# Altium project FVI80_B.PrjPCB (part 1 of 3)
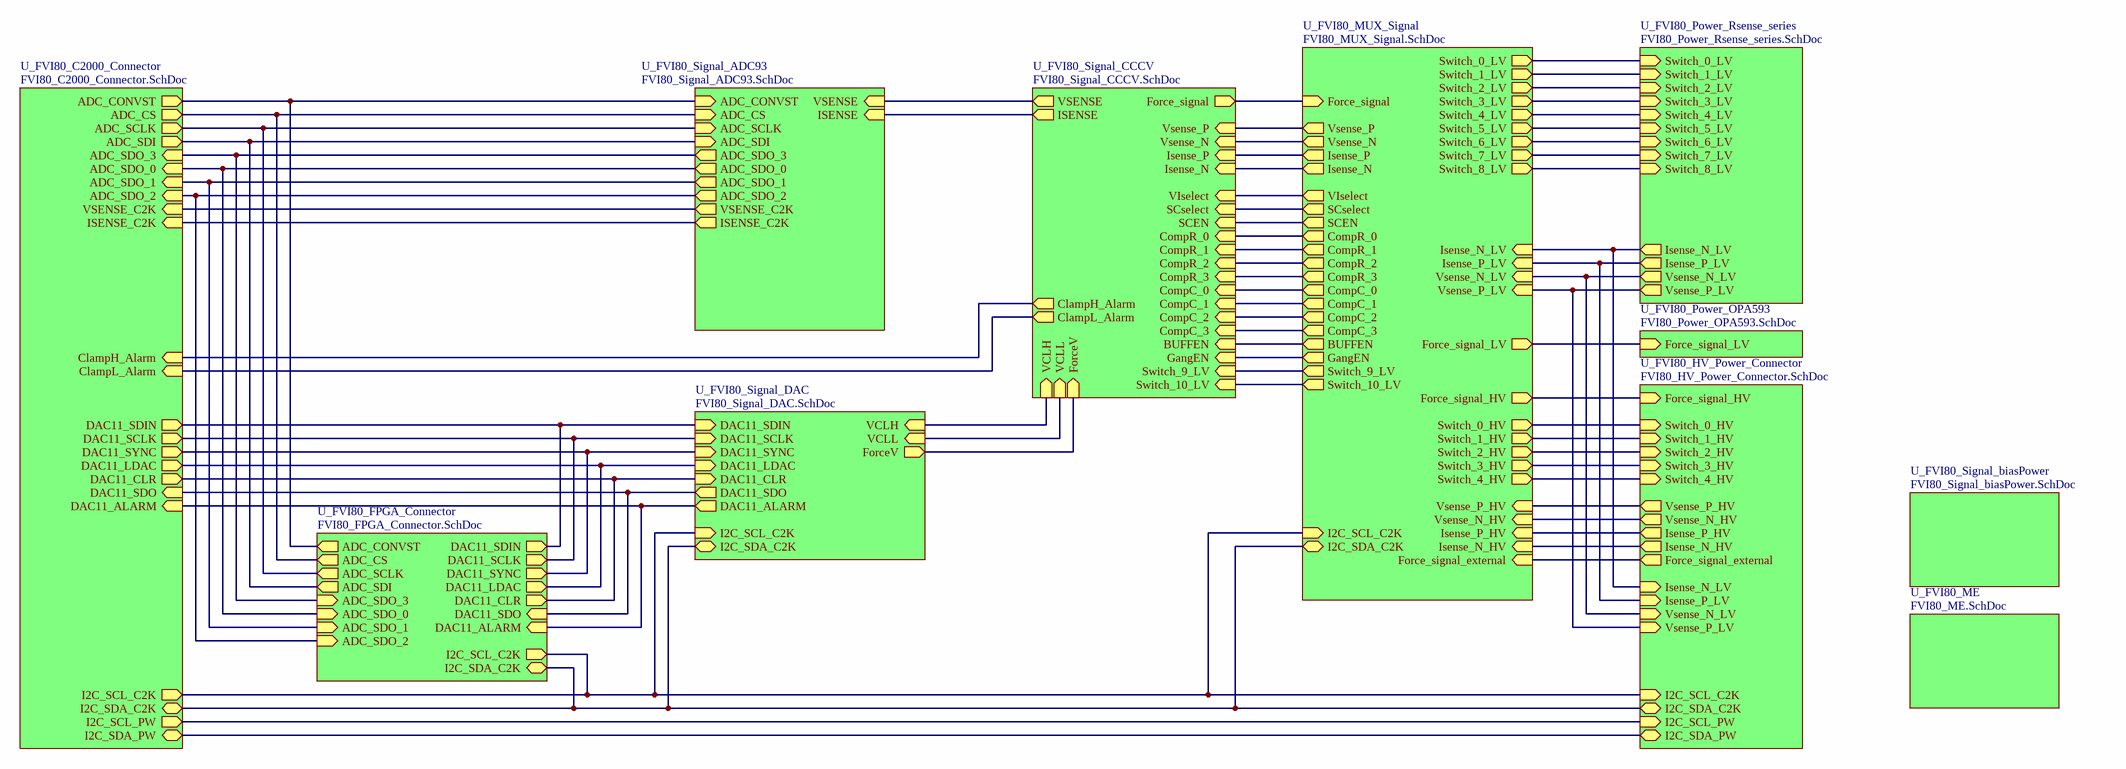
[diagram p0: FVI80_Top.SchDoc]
CopyrightYear: 2025; EVM_orderable: Developing; PCB_Rev: B; PRJ_Customer: Public Release; PRJ_Number: INDSYS-3257; PRJ_Title: FVI80 for ATE; SCH_Rev: B; TechSupport: http://www.ti.com/support; TID: TIDA-010962
12 sheets, 489 parts. Net scope: hierarchical (ports join the sheet entries above them; power ports are global).
Board file: FVI80PCB_B.PcbDoc
Sheets:
  FVI80_Top.SchDoc
    U_FVI80_ME = FVI80_ME.SchDoc
    U_FVI80_Power_OPA593 = FVI80_Power_OPA593.SchDoc
    U_FVI80_Signal_biasPower = FVI80_Signal_biasPower.SchDoc
    U_FVI80_Signal_DAC = FVI80_Signal_DAC.SchDoc
    U_FVI80_Signal_CCCV = FVI80_Signal_CCCV.SchDoc
    U_FVI80_C2000_Connector = FVI80_C2000_Connector.SchDoc
    U_FVI80_MUX_Signal = FVI80_MUX_Signal.SchDoc
    U_FVI80_HV_Power_Connector = FVI80_HV_Power_Connector.SchDoc
    U_FVI80_Signal_ADC93 = FVI80_Signal_ADC93.SchDoc
    U_FVI80_Power_Rsense_series = FVI80_Power_Rsense_series.SchDoc
    U_FVI80_FPGA_Connector = FVI80_FPGA_Connector.SchDoc

## Sheet FVI80_Top.SchDoc
size 431 x 279 mm; Date: Not shown in title block; ApprovedBy: Not shown in title block; CheckedBy: Not shown in title block; Author: Not shown in title block; CompanyName: Not shown in title block; Engineer: Not shown in title block; Organization: Not shown in title block; Address1: Not shown in title block; Address2: Not shown in title block; Address3: Not shown in title block; Address4: Not shown in title block; DocumentNumber: 1; Revision: Use project parameter SCH_Rev; SheetNumber: 1; SheetTotal: 11; PageSetup: Record=PageOptions¦CenterHorizontal=True¦CenterVertical=True¦PrintScale=1.00¦XCorrection=1.00¦YCorrection=1.00¦PrintKind=0¦BorderSize=5000000¦LeftOffset=0¦BottomOffset=0¦Orientation=2¦PaperLength=1000¦PaperWidth=1000¦Scale=100¦PaperSource=15¦PrintQuality=600¦MediaType=1¦DitherType=10¦PaperKind=Letter¦PrintScaleMode=1

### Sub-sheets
U_FVI80_C2000_Connector = FVI80_C2000_Connector.SchDoc: DAC11_SCLK (out), DAC11_SDIN (out), DAC11_SDO (in), DAC11_SYNC (out), DAC11_LDAC (out), DAC11_CLR (out), DAC11_ALARM (in), I2C_SDA_C2K (bidir), I2C_SCL_C2K (out), VSENSE_C2K (in), ISENSE_C2K (in), I2C_SDA_PW (bidir), I2C_SCL_PW (out), ADC_SDO_3 (in), ADC_SDI (out), ADC_SCLK (out), ADC_CS (out), ADC_SDO_1 (in), ADC_SDO_0 (in), ADC_SDO_2 (in), ADC_CONVST (out), ClampH_Alarm (in), ClampL_Alarm (in)
U_FVI80_FPGA_Connector = FVI80_FPGA_Connector.SchDoc: ADC_SDO_3 (in), ADC_SDI (out), ADC_SCLK (out), ADC_CS (out), ADC_SDO_1 (in), ADC_CONVST (out), ADC_SDO_0 (in), ADC_SDO_2 (in), DAC11_SCLK (out), DAC11_SDIN (out), DAC11_SDO (in), DAC11_SYNC (out), DAC11_LDAC (out), DAC11_CLR (out), DAC11_ALARM (in), I2C_SCL_C2K (out), I2C_SDA_C2K (bidir)
U_FVI80_HV_Power_Connector = FVI80_HV_Power_Connector.SchDoc: Isense_N_HV (out), Vsense_N_HV (out), Vsense_P_HV (out), Isense_P_HV (out), I2C_SCL_C2K (in), I2C_SDA_C2K (bidir), I2C_SDA_PW (bidir), I2C_SCL_PW (in), Switch_0_HV (in), Switch_1_HV (in), Switch_2_HV (in), Force_signal_HV (in), Force_signal_external (out), Isense_N_LV (in), Isense_P_LV (in), Vsense_N_LV (in), Vsense_P_LV (in), Switch_4_HV (in), Switch_3_HV (in)
U_FVI80_ME = FVI80_ME.SchDoc: no entries
U_FVI80_MUX_Signal = FVI80_MUX_Signal.SchDoc: Isense_N (out), Isense_P (out), Vsense_N (out), Vsense_P (out), CompR_0 (out), CompR_1 (out), CompR_2 (out), CompR_3 (out), CompC_0 (out), CompC_1 (out), CompC_2 (out), CompC_3 (out), Force_signal_HV (out), Force_signal_LV (out), VIselect (out), SCselect (out), I2C_SCL_C2K (in), I2C_SDA_C2K (bidir), Force_signal (in), Force_signal_external (in), Switch_0_HV (out), Switch_1_HV (out), Switch_2_HV (out), Isense_N_HV (in), Isense_P_HV (in), Vsense_N_HV (in), Vsense_P_HV (in), Switch_0_LV (out), Switch_1_LV (out), Switch_2_LV (out), Switch_3_LV (out), Switch_4_LV (out), Switch_5_LV (out), Switch_6_LV (out), Switch_7_LV (out), Switch_8_LV (out), Isense_N_LV (in), Isense_P_LV (in), Vsense_N_LV (in), Vsense_P_LV (in), Switch_9_LV (out), Switch_10_LV (out), Switch_4_HV (out), Switch_3_HV (out), SCEN (out), GangEN (out), BUFFEN (out)
U_FVI80_Power_OPA593 = FVI80_Power_OPA593.SchDoc: Force_signal_LV (in)
U_FVI80_Power_Rsense_series = FVI80_Power_Rsense_series.SchDoc: Switch_0_LV (in), Switch_1_LV (in), Switch_2_LV (in), Switch_3_LV (in), Switch_4_LV (in), Switch_5_LV (in), Switch_6_LV (in), Switch_7_LV (in), Switch_8_LV (in), Isense_N_LV (out), Isense_P_LV (out), Vsense_N_LV (out), Vsense_P_LV (out)
U_FVI80_Signal_ADC93 = FVI80_Signal_ADC93.SchDoc: VSENSE (in), ISENSE (in), VSENSE_C2K (out), ISENSE_C2K (out), ADC_SDO_3 (out), ADC_SDI (in), ADC_SCLK (in), ADC_CS (in), ADC_SDO_1 (out), ADC_CONVST (in), ADC_SDO_0 (out), ADC_SDO_2 (out)
U_FVI80_Signal_biasPower = FVI80_Signal_biasPower.SchDoc: no entries
U_FVI80_Signal_CCCV = FVI80_Signal_CCCV.SchDoc: Vsense_N (in), Vsense_P (in), VIselect (in), Isense_N (in), Isense_P (in), SCselect (in), VCLH (in), VCLL (in), Force_signal (out), ForceV (in), CompR_0 (in), CompR_1 (in), CompR_2 (in), CompR_3 (in), CompC_0 (in), CompC_1 (in), CompC_2 (in), CompC_3 (in), VSENSE (out), ISENSE (out), Switch_9_LV (in), Switch_10_LV (in), SCEN (in), ClampH_Alarm (out), ClampL_Alarm (out), GangEN (in), BUFFEN (in)
U_FVI80_Signal_DAC = FVI80_Signal_DAC.SchDoc: ForceV (out), DAC11_SCLK (in), DAC11_SDIN (in), DAC11_SDO (out), DAC11_SYNC (in), DAC11_LDAC (in), DAC11_CLR (in), DAC11_ALARM (out), I2C_SCL_C2K (in), I2C_SDA_C2K (bidir), VCLH (in), VCLL (in)

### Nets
I2C_SCL_IN: sheet U_FVI80_Signal_DAC/I2C_SCL_C2K, sheet U_FVI80_C2000_Connector/I2C_SCL_C2K, sheet U_FVI80_MUX_Signal/I2C_SCL_C2K, sheet U_FVI80_HV_Power_Connector/I2C_SCL_C2K, sheet U_FVI80_FPGA_Connector/I2C_SCL_C2K
I2C_SDA_IN: sheet U_FVI80_Signal_DAC/I2C_SDA_C2K, sheet U_FVI80_C2000_Connector/I2C_SDA_C2K, sheet U_FVI80_MUX_Signal/I2C_SDA_C2K, sheet U_FVI80_HV_Power_Connector/I2C_SDA_C2K, sheet U_FVI80_FPGA_Connector/I2C_SDA_C2K
NetC19_1: sheet U_FVI80_Signal_CCCV/ISENSE, sheet U_FVI80_Signal_ADC93/ISENSE
NetC36_1: sheet U_FVI80_Signal_CCCV/VSENSE, sheet U_FVI80_Signal_ADC93/VSENSE
NetC39_2: sheet U_FVI80_Signal_CCCV/Force_signal, sheet U_FVI80_MUX_Signal/Force_signal
NetC56_1: sheet U_FVI80_Signal_DAC/ForceV, sheet U_FVI80_Signal_CCCV/ForceV
NetD1_2: sheet U_FVI80_MUX_Signal/Isense_N_LV, sheet U_FVI80_HV_Power_Connector/Isense_N_LV, sheet U_FVI80_Power_Rsense_series/Isense_N_LV
NetD2_2: sheet U_FVI80_MUX_Signal/Isense_P_LV, sheet U_FVI80_HV_Power_Connector/Isense_P_LV, sheet U_FVI80_Power_Rsense_series/Isense_P_LV
NetD3_2: sheet U_FVI80_MUX_Signal/Vsense_P_LV, sheet U_FVI80_HV_Power_Connector/Vsense_P_LV, sheet U_FVI80_Power_Rsense_series/Vsense_P_LV
NetD4_1: sheet U_FVI80_MUX_Signal/Vsense_N_LV, sheet U_FVI80_HV_Power_Connector/Vsense_N_LV, sheet U_FVI80_Power_Rsense_series/Vsense_N_LV
NetK1_2: sheet U_FVI80_MUX_Signal/Switch_2_LV, sheet U_FVI80_Power_Rsense_series/Switch_2_LV
NetK2_2: sheet U_FVI80_MUX_Signal/Switch_0_LV, sheet U_FVI80_Power_Rsense_series/Switch_0_LV
NetK3_2: sheet U_FVI80_MUX_Signal/Switch_1_LV, sheet U_FVI80_Power_Rsense_series/Switch_1_LV
NetK4_2: sheet U_FVI80_MUX_Signal/Switch_3_LV, sheet U_FVI80_Power_Rsense_series/Switch_3_LV
NetK5_2: sheet U_FVI80_MUX_Signal/Switch_4_LV, sheet U_FVI80_Power_Rsense_series/Switch_4_LV
NetK6_2: sheet U_FVI80_MUX_Signal/Switch_5_LV, sheet U_FVI80_Power_Rsense_series/Switch_5_LV
NetK7_2: sheet U_FVI80_MUX_Signal/Switch_6_LV, sheet U_FVI80_Power_Rsense_series/Switch_6_LV
NetK8_2: sheet U_FVI80_MUX_Signal/Switch_8_LV, sheet U_FVI80_Power_Rsense_series/Switch_8_LV
NetK9_2: sheet U_FVI80_MUX_Signal/Switch_7_LV, sheet U_FVI80_Power_Rsense_series/Switch_7_LV
NetR3_1: sheet U_FVI80_Power_OPA593/Force_signal_LV, sheet U_FVI80_MUX_Signal/Force_signal_LV
NetR52_1: sheet U_FVI80_Signal_CCCV/Isense_N, sheet U_FVI80_MUX_Signal/Isense_N
NetR58_1: sheet U_FVI80_Signal_CCCV/Isense_P, sheet U_FVI80_MUX_Signal/Isense_P
NetR62_1: sheet U_FVI80_Signal_DAC/VCLL, sheet U_FVI80_Signal_CCCV/VCLL
NetR91_1: sheet U_FVI80_Signal_CCCV/Vsense_N, sheet U_FVI80_MUX_Signal/Vsense_N
NetR93_1: sheet U_FVI80_Signal_CCCV/Vsense_P, sheet U_FVI80_MUX_Signal/Vsense_P
NetR114_1: sheet U_FVI80_MUX_Signal/Force_signal_external, sheet U_FVI80_HV_Power_Connector/Force_signal_external
NetR115_1: sheet U_FVI80_Signal_DAC/DAC11_ALARM, sheet U_FVI80_C2000_Connector/DAC11_ALARM, sheet U_FVI80_FPGA_Connector/DAC11_ALARM
NetR116_1: sheet U_FVI80_Signal_DAC/DAC11_CLR, sheet U_FVI80_C2000_Connector/DAC11_CLR, sheet U_FVI80_FPGA_Connector/DAC11_CLR
NetR117_1: sheet U_FVI80_Signal_DAC/DAC11_LDAC, sheet U_FVI80_C2000_Connector/DAC11_LDAC, sheet U_FVI80_FPGA_Connector/DAC11_LDAC
NetR118_1: sheet U_FVI80_Signal_DAC/DAC11_SYNC, sheet U_FVI80_C2000_Connector/DAC11_SYNC, sheet U_FVI80_FPGA_Connector/DAC11_SYNC
NetR128_2: sheet U_FVI80_Signal_DAC/VCLH, sheet U_FVI80_Signal_CCCV/VCLH
NetR134_1: sheet U_FVI80_C2000_Connector/ADC_CONVST, sheet U_FVI80_Signal_ADC93/ADC_CONVST, sheet U_FVI80_FPGA_Connector/ADC_CONVST
NetR134_2: sheet U_FVI80_C2000_Connector/ADC_CS, sheet U_FVI80_Signal_ADC93/ADC_CS, sheet U_FVI80_FPGA_Connector/ADC_CS
NetR163_2: sheet U_FVI80_C2000_Connector/ISENSE_C2K, sheet U_FVI80_Signal_ADC93/ISENSE_C2K
NetR165_2: sheet U_FVI80_Signal_CCCV/ClampH_Alarm, sheet U_FVI80_C2000_Connector/ClampH_Alarm
NetR166_2: sheet U_FVI80_Signal_CCCV/ClampL_Alarm, sheet U_FVI80_C2000_Connector/ClampL_Alarm
NetR167_2: sheet U_FVI80_C2000_Connector/VSENSE_C2K, sheet U_FVI80_Signal_ADC93/VSENSE_C2K
NetR169_1: sheet U_FVI80_C2000_Connector/I2C_SDA_PW, sheet U_FVI80_HV_Power_Connector/I2C_SDA_PW
NetR170_2: sheet U_FVI80_C2000_Connector/ADC_SDO_0, sheet U_FVI80_Signal_ADC93/ADC_SDO_0, sheet U_FVI80_FPGA_Connector/ADC_SDO_0
NetR171_1: sheet U_FVI80_C2000_Connector/I2C_SCL_PW, sheet U_FVI80_HV_Power_Connector/I2C_SCL_PW
NetR172_2: sheet U_FVI80_C2000_Connector/ADC_SDO_1, sheet U_FVI80_Signal_ADC93/ADC_SDO_1, sheet U_FVI80_FPGA_Connector/ADC_SDO_1
NetR174_2: sheet U_FVI80_C2000_Connector/ADC_SDO_2, sheet U_FVI80_Signal_ADC93/ADC_SDO_2, sheet U_FVI80_FPGA_Connector/ADC_SDO_2
NetR178_1: sheet U_FVI80_C2000_Connector/ADC_SDI, sheet U_FVI80_Signal_ADC93/ADC_SDI, sheet U_FVI80_FPGA_Connector/ADC_SDI
NetR179_1: sheet U_FVI80_C2000_Connector/ADC_SDO_3, sheet U_FVI80_Signal_ADC93/ADC_SDO_3, sheet U_FVI80_FPGA_Connector/ADC_SDO_3
NetR181_1: sheet U_FVI80_C2000_Connector/ADC_SCLK, sheet U_FVI80_Signal_ADC93/ADC_SCLK, sheet U_FVI80_FPGA_Connector/ADC_SCLK
NetR185_1: sheet U_FVI80_Signal_DAC/DAC11_SDIN, sheet U_FVI80_C2000_Connector/DAC11_SDIN, sheet U_FVI80_FPGA_Connector/DAC11_SDIN
NetR186_1: sheet U_FVI80_Signal_DAC/DAC11_SDO, sheet U_FVI80_C2000_Connector/DAC11_SDO, sheet U_FVI80_FPGA_Connector/DAC11_SDO
NetR187_1: sheet U_FVI80_Signal_DAC/DAC11_SCLK, sheet U_FVI80_C2000_Connector/DAC11_SCLK, sheet U_FVI80_FPGA_Connector/DAC11_SCLK
NetR197_2: sheet U_FVI80_MUX_Signal/Switch_0_HV, sheet U_FVI80_HV_Power_Connector/Switch_0_HV
NetR199_2: sheet U_FVI80_MUX_Signal/Switch_1_HV, sheet U_FVI80_HV_Power_Connector/Switch_1_HV
NetR200_1: sheet U_FVI80_MUX_Signal/Isense_P_HV, sheet U_FVI80_HV_Power_Connector/Isense_P_HV
NetR201_2: sheet U_FVI80_MUX_Signal/Switch_2_HV, sheet U_FVI80_HV_Power_Connector/Switch_2_HV
NetR202_1: sheet U_FVI80_MUX_Signal/Isense_N_HV, sheet U_FVI80_HV_Power_Connector/Isense_N_HV
NetR203_2: sheet U_FVI80_MUX_Signal/Switch_3_HV, sheet U_FVI80_HV_Power_Connector/Switch_3_HV
NetR205_1: sheet U_FVI80_MUX_Signal/Vsense_P_HV, sheet U_FVI80_HV_Power_Connector/Vsense_P_HV
NetR206_2: sheet U_FVI80_MUX_Signal/Switch_4_HV, sheet U_FVI80_HV_Power_Connector/Switch_4_HV
NetR207_1: sheet U_FVI80_MUX_Signal/Vsense_N_HV, sheet U_FVI80_HV_Power_Connector/Vsense_N_HV
NetR209_1: sheet U_FVI80_MUX_Signal/Force_signal_HV, sheet U_FVI80_HV_Power_Connector/Force_signal_HV
NetU11_6: sheet U_FVI80_Signal_CCCV/BUFFEN, sheet U_FVI80_MUX_Signal/BUFFEN
NetU16_6: sheet U_FVI80_Signal_CCCV/VIselect, sheet U_FVI80_MUX_Signal/VIselect
NetU17_6: sheet U_FVI80_Signal_CCCV/Switch_9_LV, sheet U_FVI80_MUX_Signal/Switch_9_LV
NetU18_6: sheet U_FVI80_Signal_CCCV/SCselect, sheet U_FVI80_MUX_Signal/SCselect
NetU18_12: sheet U_FVI80_Signal_CCCV/SCEN, sheet U_FVI80_MUX_Signal/SCEN
NetU20_5: sheet U_FVI80_Signal_CCCV/GangEN, sheet U_FVI80_MUX_Signal/GangEN
NetU20_6: sheet U_FVI80_Signal_CCCV/Switch_10_LV, sheet U_FVI80_MUX_Signal/Switch_10_LV
NetU21_6: sheet U_FVI80_Signal_CCCV/CompR_3, sheet U_FVI80_MUX_Signal/CompR_3
NetU21_7: sheet U_FVI80_Signal_CCCV/CompR_2, sheet U_FVI80_MUX_Signal/CompR_2
NetU21_14: sheet U_FVI80_Signal_CCCV/CompR_1, sheet U_FVI80_MUX_Signal/CompR_1
NetU21_15: sheet U_FVI80_Signal_CCCV/CompR_0, sheet U_FVI80_MUX_Signal/CompR_0
NetU22_6: sheet U_FVI80_Signal_CCCV/CompC_3, sheet U_FVI80_MUX_Signal/CompC_3
NetU22_7: sheet U_FVI80_Signal_CCCV/CompC_2, sheet U_FVI80_MUX_Signal/CompC_2
NetU22_14: sheet U_FVI80_Signal_CCCV/CompC_1, sheet U_FVI80_MUX_Signal/CompC_1
NetU22_15: sheet U_FVI80_Signal_CCCV/CompC_0, sheet U_FVI80_MUX_Signal/CompC_0

## Sheet FVI80_ME.SchDoc
size 431 x 279 mm; Date: Not shown in title block; ApprovedBy: Not shown in title block; CheckedBy: Not shown in title block; Author: Not shown in title block; CompanyName: Not shown in title block; Engineer: Not shown in title block; Organization: Not shown in title block; Address1: Not shown in title block; Address2: Not shown in title block; Address3: Not shown in title block; Address4: Not shown in title block; DocumentNumber: 11; Revision: Use project parameter SCH_Rev; SheetNumber: 11; SheetTotal: 11; PageSetup: Record=PageOptions¦CenterHorizontal=True¦CenterVertical=True¦PrintScale=1.00¦XCorrection=1.00¦YCorrection=1.00¦PrintKind=0¦BorderSize=5000000¦LeftOffset=0¦BottomOffset=0¦Orientation=2¦PaperLength=1000¦PaperWidth=1000¦Scale=100¦PaperSource=15¦PrintQuality=600¦MediaType=1¦DitherType=10¦PaperKind=Letter¦PrintScaleMode=1
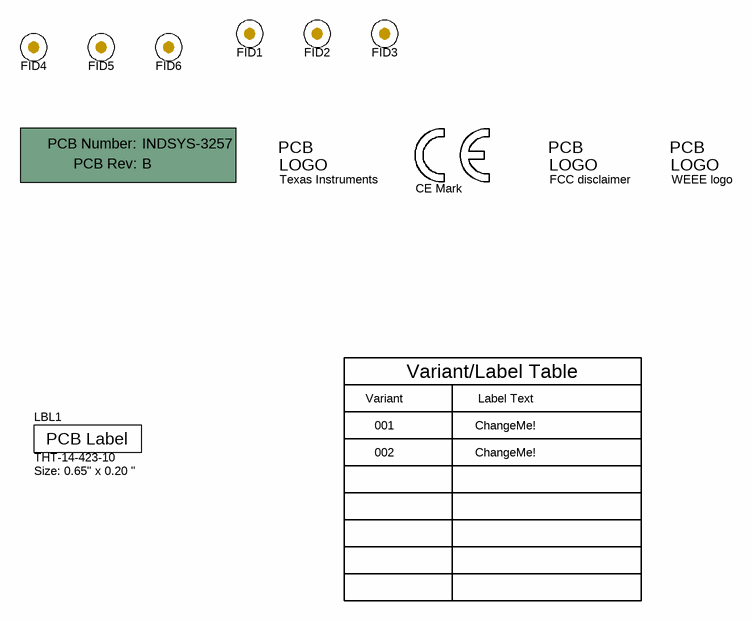
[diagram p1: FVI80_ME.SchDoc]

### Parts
!PCB1  Printed Circuit Board  (value not drawn)  (mechanical)
FID1  Fiducial  [Fiducial10-20]  (value not drawn)
FID2  Fiducial  [Fiducial10-20]  (value not drawn)
FID3  Fiducial  [Fiducial10-20]  (value not drawn)
FID4  Fiducial  [Fiducial10-20]  (value not drawn)
FID5  Fiducial  [Fiducial10-20]  (value not drawn)
FID6  Fiducial  [Fiducial10-20]  (value not drawn)
LBL1  THT-14-423-10  Note: Size: 0.65" x 0.20 "  [Label_650x200]
Logo1  CE Mark  [CE_Mark_5mm]  (no BOM)
Logo2  Texas Instruments  [TI_Stacked_Overlay_Small]  (no BOM)
Logo3  FCC disclaimer  [FCC_disclaimer]  (no BOM)
Logo4  WEEE logo  [WEEE_Minimum]  (no BOM)

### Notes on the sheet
- Variant
- Variant/Label Table
- Label Text
- 001
- 002
- ChangeMe!

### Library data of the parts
!PCB1 = CMP-0003618-2: Manufacturer: Any
FID1-FID6 = CMP-0077181-1: Fiducial mark.  There is nothing to buy or mount.
LBL1 = CMP-0003625-1: Thermal Transfer Printable Labels, 0.650" W x 0.200" H - 10,000 per roll; Manufacturer: Brady; CompType: Label
Logo1 = CMP-0074844-1: SymbolCreator: a0412235
Logo2 = CMP-0074838-1: Texas Instrument Corporate Signature; SymbolCreator: a0412235; Lib Reference: TI_Logo; Library Reference: Logo
Logo3 = CMP-0074847-1: FCC_disclaimer; Library Reference: Logo
Logo4 = CMP-0074769-3: Manufacturer: Texas Instruments; CompType: IC; AEC Category: Q200

## Sheet FVI80_Power_OPA593.SchDoc
size 431 x 279 mm; Date: Not shown in title block; ApprovedBy: Not shown in title block; CheckedBy: Not shown in title block; Author: Not shown in title block; CompanyName: Not shown in title block; Engineer: Not shown in title block; Organization: Not shown in title block; Address1: Not shown in title block; Address2: Not shown in title block; Address3: Not shown in title block; Address4: Not shown in title block; DocumentNumber: 2; Revision: Use project parameter SCH_Rev; SheetNumber: 2; SheetTotal: 11; PageSetup: Record=PageOptions¦CenterHorizontal=True¦CenterVertical=True¦PrintScale=1.00¦XCorrection=1.00¦YCorrection=1.00¦PrintKind=0¦BorderSize=5000000¦LeftOffset=0¦BottomOffset=0¦Orientation=2¦PaperLength=1000¦PaperWidth=1000¦Scale=100¦PaperSource=15¦PrintQuality=600¦MediaType=1¦DitherType=10¦PaperKind=Letter¦PrintScaleMode=1
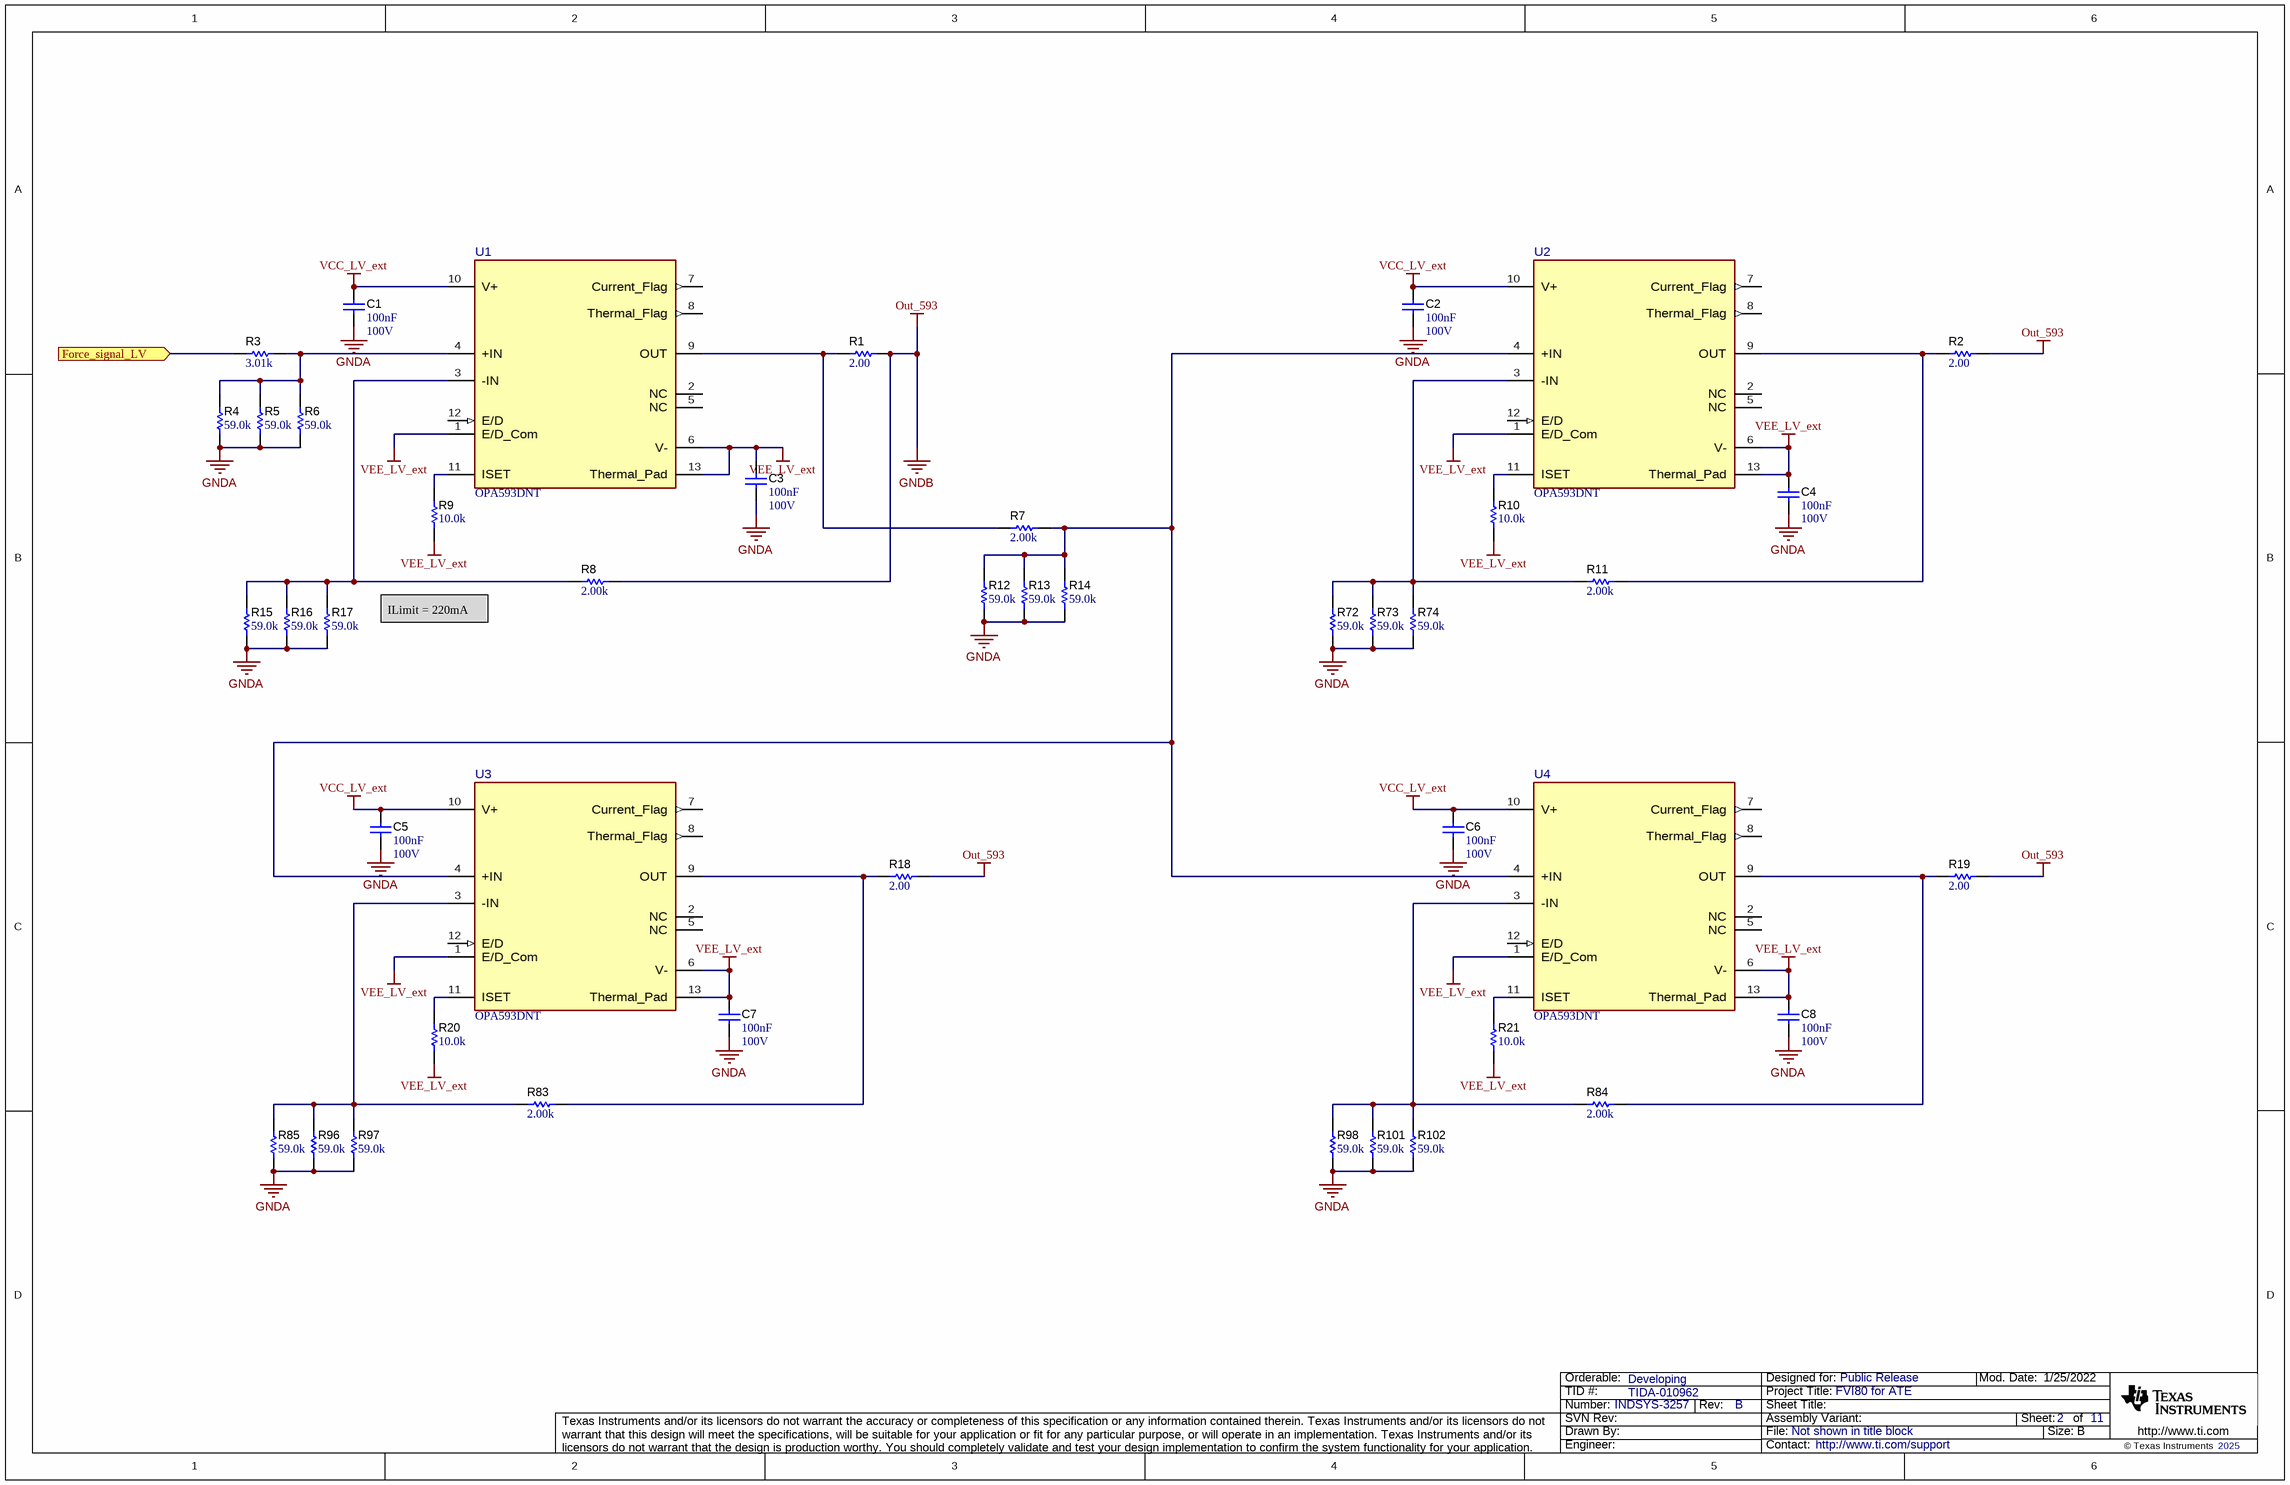
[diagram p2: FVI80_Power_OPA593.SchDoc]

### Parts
C1  Cap_F: 100nF  VDC_V: 100V  [0402]  (hidden comment: GRM155R62A104KE14D)
C2  Cap_F: 100nF  VDC_V: 100V  [0402]  (hidden comment: GRM155R62A104KE14D)
C3  Cap_F: 100nF  VDC_V: 100V  [0402]  (hidden comment: GRM155R62A104KE14D)
C4  Cap_F: 100nF  VDC_V: 100V  [0402]  (hidden comment: GRM155R62A104KE14D)
C5  Cap_F: 100nF  VDC_V: 100V  [0402]  (hidden comment: GRM155R62A104KE14D)
C6  Cap_F: 100nF  VDC_V: 100V  [0402]  (hidden comment: GRM155R62A104KE14D)
C7  Cap_F: 100nF  VDC_V: 100V  [0402]  (hidden comment: GRM155R62A104KE14D)
C8  Cap_F: 100nF  VDC_V: 100V  [0402]  (hidden comment: GRM155R62A104KE14D)
R1  ValueDisplayed: 2.00  [0805_HV]  (hidden comment: CRCW08052R00FKEA)
R2  ValueDisplayed: 2.00  [0805_HV]  (hidden comment: CRCW08052R00FKEA)
R3  ValueDisplayed: 3.01k  [0603]  (hidden comment: CRCW06033K01FKEA)
R4  ValueDisplayed: 59.0k  [0805_HV]  (hidden comment: CRCW080559K0FKEA)
R5  ValueDisplayed: 59.0k  [0805_HV]  (hidden comment: CRCW080559K0FKEA)
R6  ValueDisplayed: 59.0k  [0805_HV]  (hidden comment: CRCW080559K0FKEA)
R7  ValueDisplayed: 2.00k  [0603]  (hidden comment: CRCW06032K00FKEA)
R8  ValueDisplayed: 2.00k  [0603]  (hidden comment: CRCW06032K00FKEA)
R9  ValueDisplayed: 10.0k  [0402]  (hidden comment: RK73H1ETTP1002F)
R10  ValueDisplayed: 10.0k  [0402]  (hidden comment: RK73H1ETTP1002F)
R11  ValueDisplayed: 2.00k  [0603]  (hidden comment: CRCW06032K00FKEA)
R12  ValueDisplayed: 59.0k  [0805_HV]  (hidden comment: CRCW080559K0FKEA)
R13  ValueDisplayed: 59.0k  [0805_HV]  (hidden comment: CRCW080559K0FKEA)
R14  ValueDisplayed: 59.0k  [0805_HV]  (hidden comment: CRCW080559K0FKEA)
R15  ValueDisplayed: 59.0k  [0805_HV]  (hidden comment: CRCW080559K0FKEA)
R16  ValueDisplayed: 59.0k  [0805_HV]  (hidden comment: CRCW080559K0FKEA)
R17  ValueDisplayed: 59.0k  [0805_HV]  (hidden comment: CRCW080559K0FKEA)
R18  ValueDisplayed: 2.00  [0805_HV]  (hidden comment: CRCW08052R00FKEA)
R19  ValueDisplayed: 2.00  [0805_HV]  (hidden comment: CRCW08052R00FKEA)
R20  ValueDisplayed: 10.0k  [0402]  (hidden comment: RK73H1ETTP1002F)
R21  ValueDisplayed: 10.0k  [0402]  (hidden comment: RK73H1ETTP1002F)
R72  ValueDisplayed: 59.0k  [0805_HV]  (hidden comment: CRCW080559K0FKEA)
R73  ValueDisplayed: 59.0k  [0805_HV]  (hidden comment: CRCW080559K0FKEA)
R74  ValueDisplayed: 59.0k  [0805_HV]  (hidden comment: CRCW080559K0FKEA)
R83  ValueDisplayed: 2.00k  [0603]  (hidden comment: CRCW06032K00FKEA)
R84  ValueDisplayed: 2.00k  [0603]  (hidden comment: CRCW06032K00FKEA)
R85  ValueDisplayed: 59.0k  [0805_HV]  (hidden comment: CRCW080559K0FKEA)
R96  ValueDisplayed: 59.0k  [0805_HV]  (hidden comment: CRCW080559K0FKEA)
R97  ValueDisplayed: 59.0k  [0805_HV]  (hidden comment: CRCW080559K0FKEA)
R98  ValueDisplayed: 59.0k  [0805_HV]  (hidden comment: CRCW080559K0FKEA)
R101  ValueDisplayed: 59.0k  [0805_HV]  (hidden comment: CRCW080559K0FKEA)
R102  ValueDisplayed: 59.0k  [0805_HV]  (hidden comment: CRCW080559K0FKEA)
U1  OPA593DNT  [DNT0012B-MFG]
U2  OPA593DNT  [DNT0012B-MFG]
U3  OPA593DNT  [DNT0012B-MFG]
U4  OPA593DNT  [DNT0012B-MFG]

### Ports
Force_signal_LV (in)

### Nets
GNDA: C1.1 C2.1 C3.1 C4.1 C5.1 C6.1 C7.1 C8.1 R4.1 R5.1 R6.1 R12.1 R13.1 R14.1 R15.1 R16.1 R17.1 R72.1 R73.1 R74.1 R85.1 R96.1 R97.1 R98.1 R101.1 R102.1
GNDB: R1.2 R2.2 R8.2 R18.2 R19.2  [also labelled Out_593]
VCC_LV_ext: C1.2 C2.2 C5.2 C6.2 U1.10(V+) U2.10(V+) U3.10(V+) U4.10(V+)
VEE_LV_ext: C3.2 C4.2 C7.2 C8.2 R9.2 R10.2 R20.2 R21.2 U1.1(E/D_Com) U1.6(V-) U1.13(Thermal_Pad) U2.1(E/D_Com) U2.6(V-) U2.13(Thermal_Pad) U3.1(E/D_Com) U3.6(V-) U3.13(Thermal_Pad) U4.1(E/D_Com) U4.6(V-) U4.13(Thermal_Pad)
NetR1_1: R1.1 R7.1 U1.9(OUT)
NetR2_1: R2.1 R11.2 U2.9(OUT)
NetR3_1: R3.1 ; port Force_signal_LV
NetR3_2: R3.2 R4.2 R5.2 R6.2 U1.4(+IN)
NetR7_2: R7.2 R12.2 R13.2 R14.2 U2.4(+IN) U3.4(+IN) U4.4(+IN)
NetR8_1: R8.1 R15.2 R16.2 R17.2 U1.3(-IN)
NetR9_1: R9.1 U1.11(ISET)
NetR10_1: R10.1 U2.11(ISET)
NetR11_1: R11.1 R72.2 R73.2 R74.2 U2.3(-IN)
NetR18_1: R18.1 R83.2 U3.9(OUT)
NetR19_1: R19.1 R84.2 U4.9(OUT)
NetR20_1: R20.1 U3.11(ISET)
NetR21_1: R21.1 U4.11(ISET)
NetR83_1: R83.1 R85.2 R96.2 R97.2 U3.3(-IN)
NetR84_1: R84.1 R98.2 R101.2 R102.2 U4.3(-IN)

Not connected (* = marked no-connect by the designer): U1 2(NC) 5(NC) 7(Current_Flag) 8(Thermal_Flag) 12(E/D); U2 2(NC) 5(NC) 7(Current_Flag) 8(Thermal_Flag) 12(E/D); U3 2(NC) 5(NC) 7(Current_Flag) 8(Thermal_Flag) 12(E/D); U4 2(NC) 5(NC) 7(Current_Flag) 8(Thermal_Flag) 12(E/D)

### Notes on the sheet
- ILimit = 220mA

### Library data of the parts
C1-C8 = CMP-0006618-2: CAP, CERM, 0.1 uF, 100 V, +/- 10%, X5R, 0402; Manufacturer: MuRata; SizeY_mm: 0.5; ValueDisplayed: 0.1uF; SizeX_mm: 1; Polarized: N; Value1: Unknown; Value: 0.1uF; TaMin_C: -55°C; SizeZ_mm: 0.6; TaMax_C: 85°C; U/M: EA; SizeAreaWB_mm2: 3; AEC Category: Q200
R1 R2 R18 R19 = CMP-0021141-3: RES, 2.00, 1%, 0.125 W, AEC-Q200 Grade 0, 0805; Manufacturer: Vishay-Dale; Power_W: 125mW; TempCo: 100 ppm/C; Value_Code: 2R00; Value: 2.00; EIA_Code: E96; Res_ohm: 2; SizeY_mm: 1.25; SizeZ_mm: 1.45; Value2: 0.125W; SizeArea_mm2: 2.5; AEC Qualified: Y; AEC Grade: 0; AEC Category: Q200; VDC_V: 150V
R3 = CMP-0022371-4: RES, 3.01 k, 1%, 0.1 W, AEC-Q200 Grade 0, 0603; Manufacturer: Vishay-Dale; Power_W: 100mW; TempCo: 100 ppm/C; Value_Code: 3k01; Value: 3.01k; EIA_Code: E96; SizeX_mm: 1.6; SizeY_mm: 0.8; SizeZ_mm: 1; Value2: 0.1W; SizeArea_mm2: 1.28; AEC Qualified: Y; VDC_V: 75V; AEC Category: Q200; AEC Grade: 0
R4-R6 R12-R17 R72-R74 R85 R96-R98 R101 R102 = CMP-0021342-3: RES, 59.0 k, 1%, 0.125 W, AEC-Q200 Grade 0, 0805; Manufacturer: Vishay-Dale; Power_W: 125mW; TempCo: 100 ppm/C; Value_Code: 59k0; Value: 59.0k; EIA_Code: E96; Res_ohm: 59k; SizeX_mm: 2; SizeY_mm: 1.25; SizeZ_mm: 1.45; Value2: 0.125W; SizeArea_mm2: 2.5; AEC Qualified: Y; VDC_V: 150V; AEC Category: Q200; AEC Grade: 0
R7 R8 R11 R83 R84 = CMP-0022268-3: RES, 2.00 k, 1%, 0.1 W, 0603; Manufacturer: Vishay-Dale; Power_W: 100mW; TempCo: 100 ppm/C; Value_Code: 2k00; U/M: EA; Value: 2.00k; EIA_Code: E96; Res_ohm: 2k; SizeX_mm: 1.6; SizeY_mm: 0.8; SizeZ_mm: 1; Value2: 0.1W; SizeArea_mm2: 1.28; VDC_V: 75V; AEC Category: Q200
R9 R10 R20 R21 = CMP-0026748-1: RES, 10.0 k, 1%, 0.063 W, AEC-Q200 Grade 0, 0402; Manufacturer: KOA Speer; Power_W: 63mW; TempCo: 100 ppm/C; Value_Code: 10k0; U/M: EA; Value: 10.0k; EIA_Code: E96; Res_ohm: 10k; SizeX_mm: 1; SizeY_mm: 0.5; SizeZ_mm: 0.6; Value2: 0.063W; AEC Qualified: Y; VDC_V: 50V; AEC Grade: 0; AEC Category: Q200
U1-U4 = CMP-0089642-1: 85V, 250 mA Output Current, Precision Operational Amplifier; Manufacturer: Texas Instruments; Input Bias Current: 0.00001uA; Input Offset Voltage: 0.01mV; SizeZ_mm: 1mm; TaMin_C: -55°C; Min Dual Supply Voltage: 5V; Response Time: 1.5us; Number Of Channels: 1; AEC Qualified: No; Nominal Supply Current: 3.25mA; Min Supply Voltage: 10V; Output Current Per Channel: 250mA; TJmax_C: +150°C; Voltage Gain: 120dB; Max Dual Supply Voltage: 42.5V; Gain Bandwidth: 10MHz; Standoff Height: 0mm; TaMax_C: +125°C

## Sheet FVI80_Signal_biasPower.SchDoc
size 431 x 279 mm; Date: Not shown in title block; ApprovedBy: Not shown in title block; CheckedBy: Not shown in title block; Author: Not shown in title block; CompanyName: Not shown in title block; Engineer: Not shown in title block; Organization: Not shown in title block; Address1: Not shown in title block; Address2: Not shown in title block; Address3: Not shown in title block; Address4: Not shown in title block; DocumentNumber: 8; Revision: Use project parameter SCH_Rev; SheetNumber: 8; SheetTotal: 11; PageSetup: Record=PageOptions¦CenterHorizontal=True¦CenterVertical=True¦PrintScale=1.00¦XCorrection=1.00¦YCorrection=1.00¦PrintKind=0¦BorderSize=5000000¦LeftOffset=0¦BottomOffset=0¦Orientation=2¦PaperLength=1000¦PaperWidth=1000¦Scale=100¦PaperSource=15¦PrintQuality=600¦MediaType=1¦DitherType=10¦PaperKind=Letter¦PrintScaleMode=1
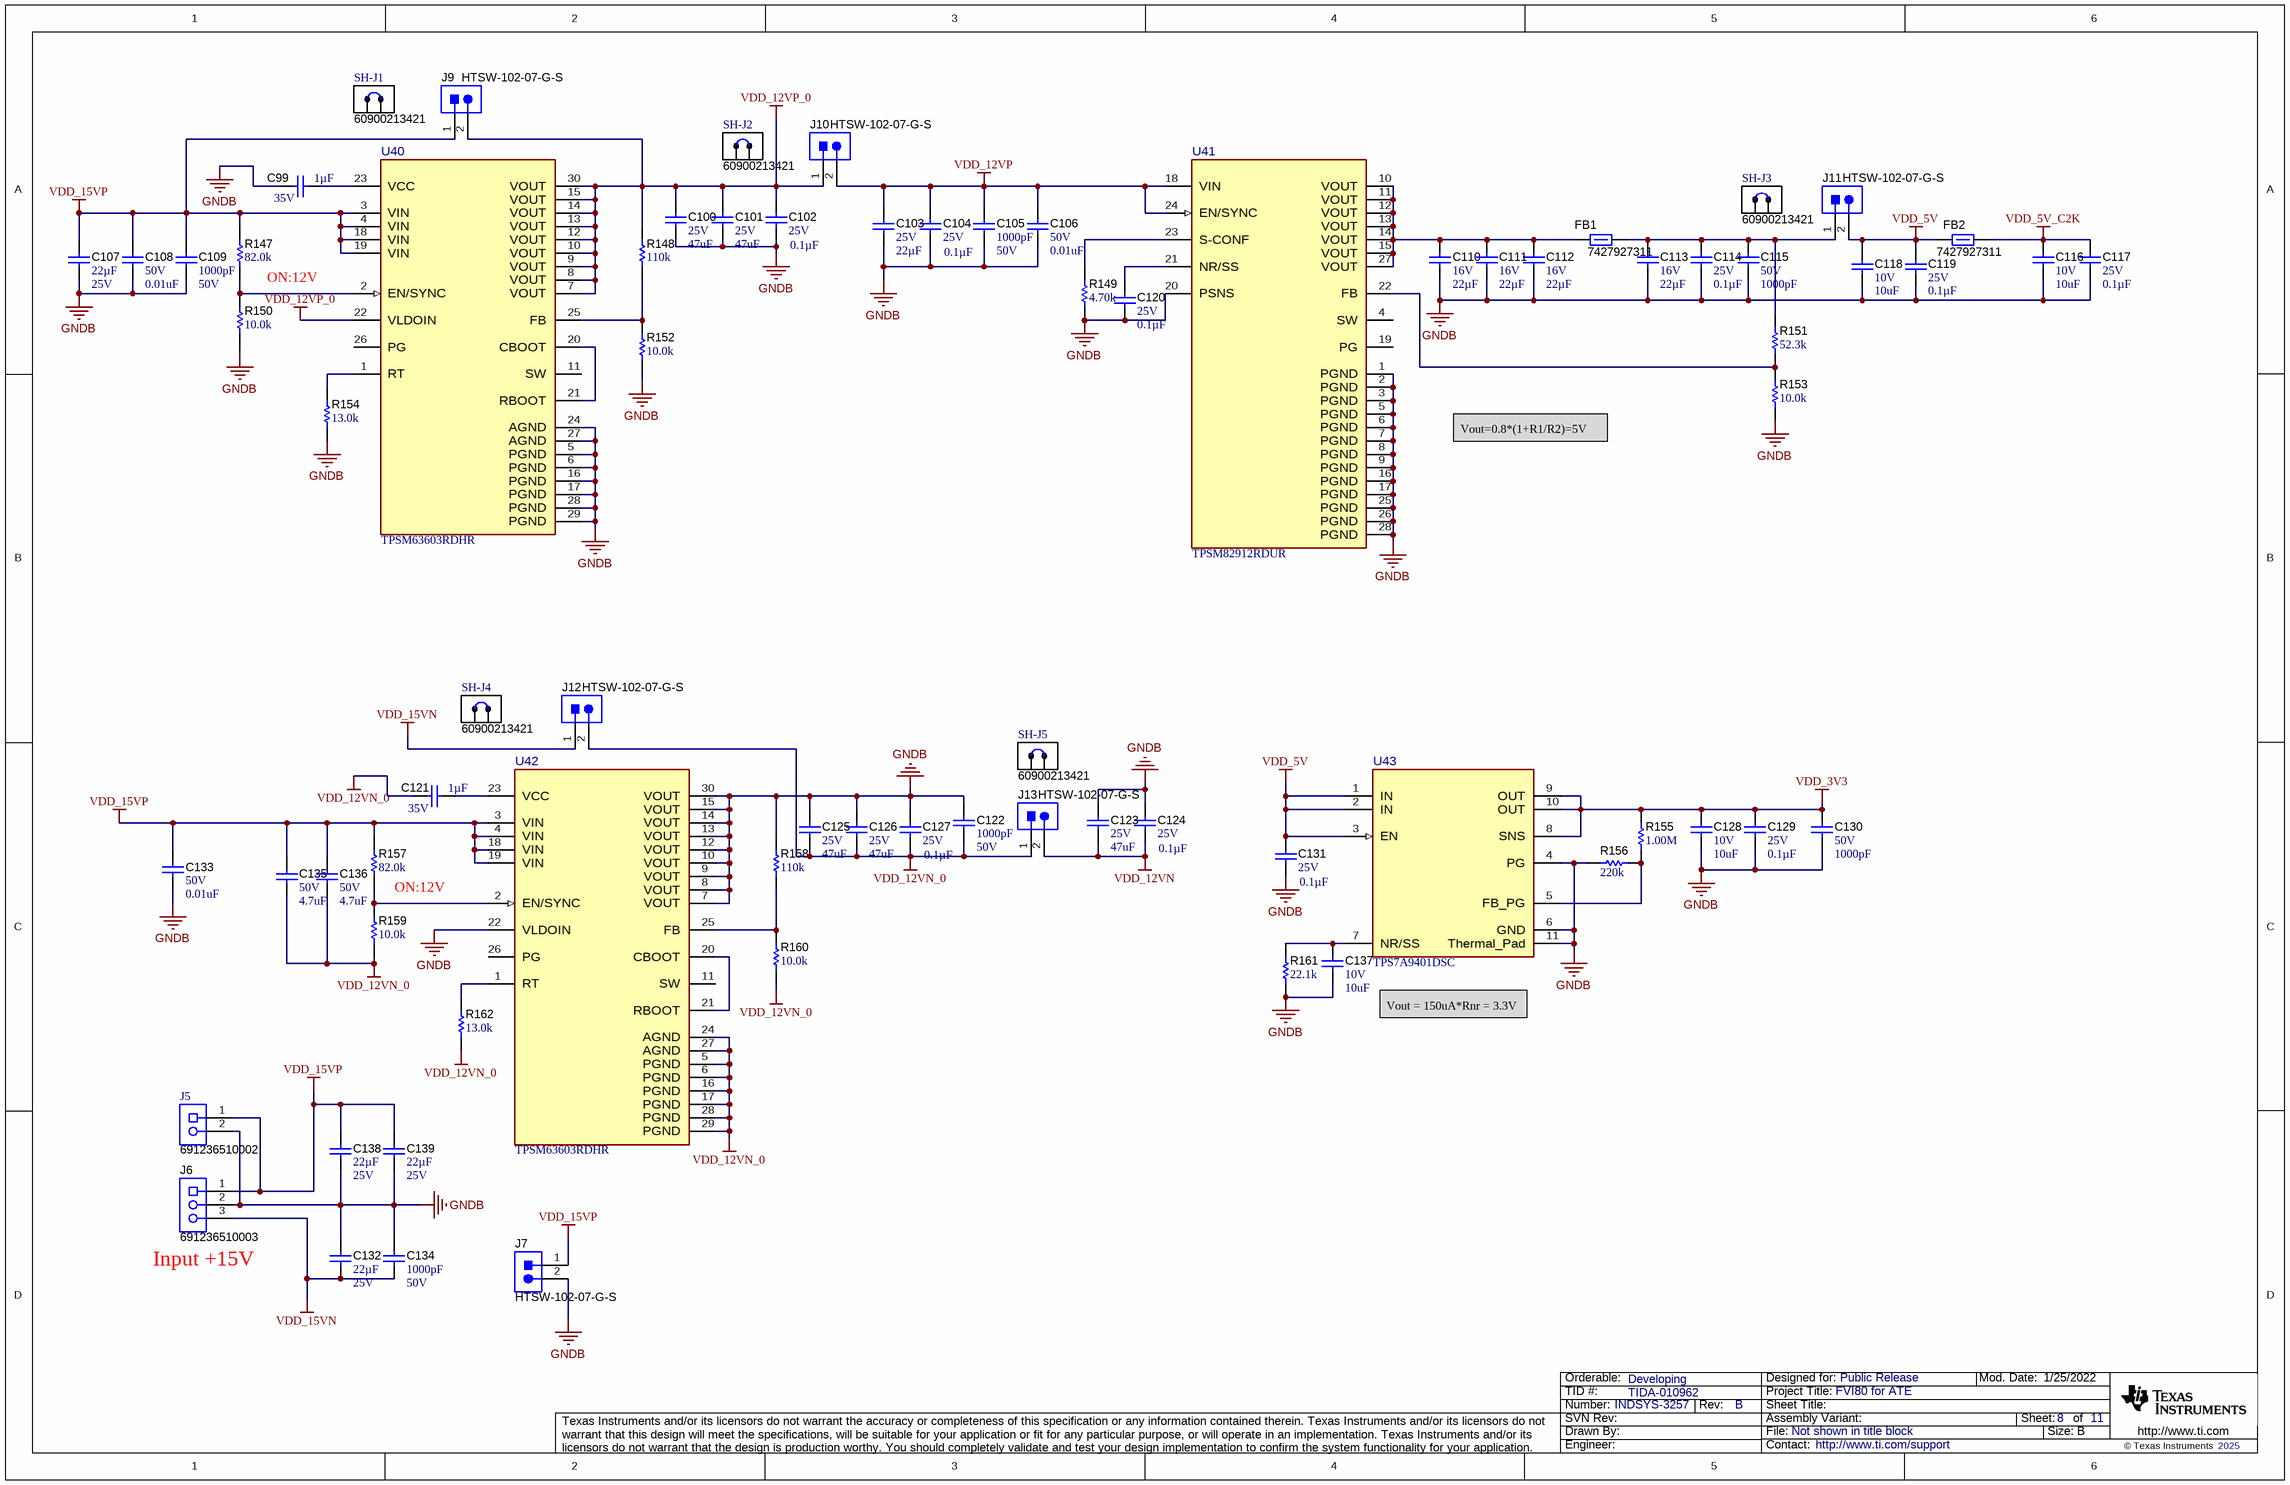
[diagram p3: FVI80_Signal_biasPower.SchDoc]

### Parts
C99  Cap_F: 1µF  VDC_V: 35V  [0603]  (hidden comment: CGA3E1X7R1V105K080AE)
C100  VDC_V: 25V  ValueDisplayed: 47uF  [1206]  (hidden comment: C3216JB1E476M160AC)
C101  VDC_V: 25V  ValueDisplayed: 47uF  [1206]  (hidden comment: C3216JB1E476M160AC)
C102  VDC_V: 25V  ValueDisplayed: 0.1µF  [0402]  (hidden comment: CGA2B3X7R1E104K050BB)
C103  VDC_V: 25V  ValueDisplayed: 22µF  [0805_HV]  (hidden comment: GRT21BR61E226ME13L)
C104  VDC_V: 25V  ValueDisplayed: 0.1µF  [0402]  (hidden comment: CGA2B3X7R1E104K050BB)
C105  ValueDisplayed: 1000pF  VDC_V: 50V  [0402]  (hidden comment: CGA2B2X8R1H102K050BA)
C106  VDC_V: 50V  ValueDisplayed: 0.01uF  [0402]  (hidden comment: GRM155R71H103KA88D)
C107  ValueDisplayed: 22µF  VDC_V: 25V  [0805_HV]  (hidden comment: GRT21BR61E226ME13L)
C108  VDC_V: 50V  ValueDisplayed: 0.01uF  [0402]  (hidden comment: GRM155R71H103KA88D)
C109  ValueDisplayed: 1000pF  VDC_V: 50V  [0402]  (hidden comment: CGA2B2X8R1H102K050BA)
C110  VDC_V: 16V  ValueDisplayed: 22µF  [0603]  (hidden comment: CL10A226MO7JZNC)
C111  VDC_V: 16V  ValueDisplayed: 22µF  [0603]  (hidden comment: CL10A226MO7JZNC)
C112  VDC_V: 16V  ValueDisplayed: 22µF  [0603]  (hidden comment: CL10A226MO7JZNC)
C113  VDC_V: 16V  ValueDisplayed: 22µF  [0603]  (hidden comment: CL10A226MO7JZNC)
C114  VDC_V: 25V  ValueDisplayed: 0.1µF  [0402]  (hidden comment: CGA2B3X7R1E104K050BB)
C115  VDC_V: 50V  ValueDisplayed: 1000pF  [0402]  (hidden comment: CGA2B2X8R1H102K050BA)
C116  VDC_V: 10V  ValueDisplayed: 10uF  [0402]  (hidden comment: GRM155R61A106ME11D)
C117  VDC_V: 25V  ValueDisplayed: 0.1µF  [0402]  (hidden comment: CGA2B3X7R1E104K050BB)
C118  VDC_V: 10V  ValueDisplayed: 10uF  [0402]  (hidden comment: GRM155R61A106ME11D)
C119  VDC_V: 25V  ValueDisplayed: 0.1µF  [0402]  (hidden comment: CGA2B3X7R1E104K050BB)
C120  VDC_V: 25V  ValueDisplayed: 0.1µF  [0402]  (hidden comment: CGA2B3X7R1E104K050BB)
C121  Cap_F: 1µF  VDC_V: 35V  [0603]  (hidden comment: CGA3E1X7R1V105K080AE)
C122  ValueDisplayed: 1000pF  VDC_V: 50V  [0402]  (hidden comment: CGA2B2X8R1H102K050BA)
C123  VDC_V: 25V  ValueDisplayed: 47uF  [1206]  (hidden comment: C3216JB1E476M160AC)
C124  VDC_V: 25V  ValueDisplayed: 0.1µF  [0402]  (hidden comment: CGA2B3X7R1E104K050BB)
C125  VDC_V: 25V  ValueDisplayed: 47uF  [1206]  (hidden comment: C3216JB1E476M160AC)
C126  VDC_V: 25V  ValueDisplayed: 47uF  [1206]  (hidden comment: C3216JB1E476M160AC)
C127  VDC_V: 25V  ValueDisplayed: 0.1µF  [0402]  (hidden comment: CGA2B3X7R1E104K050BB)
C128  VDC_V: 10V  ValueDisplayed: 10uF  [0402]  (hidden comment: GRM155R61A106ME11D)
C129  VDC_V: 25V  ValueDisplayed: 0.1µF  [0402]  (hidden comment: CGA2B3X7R1E104K050BB)
C130  VDC_V: 50V  ValueDisplayed: 1000pF  [0402]  (hidden comment: CGA2B2X8R1H102K050BA)
C131  VDC_V: 25V  ValueDisplayed: 0.1µF  [0402]  (hidden comment: CGA2B3X7R1E104K050BB)
C132  ValueDisplayed: 22µF  VDC_V: 25V  [0805_HV]  (hidden comment: GRT21BR61E226ME13L)
C133  VDC_V: 50V  ValueDisplayed: 0.01uF  [0402]  (hidden comment: GRM155R71H103KA88D)
C134  ValueDisplayed: 1000pF  VDC_V: 50V  [0402]  (hidden comment: CGA2B2X8R1H102K050BA)
C135  VDC_V: 50V  ValueDisplayed: 4.7uF  [0805_HV]  (hidden comment: C2012X6S1H475K125AC)
C136  VDC_V: 50V  ValueDisplayed: 4.7uF  [0805_HV]  (hidden comment: C2012X6S1H475K125AC)
C137  VDC_V: 10V  ValueDisplayed: 10uF  [0402]  (hidden comment: GRM155R61A106ME11D)
C138  ValueDisplayed: 22µF  VDC_V: 25V  [0805_HV]  (hidden comment: GRT21BR61E226ME13L)
C139  ValueDisplayed: 22µF  VDC_V: 25V  [0805_HV]  (hidden comment: GRT21BR61E226ME13L)
FB1  7427927311  [0402]
FB2  7427927311  [0402]
J5  691236510002  [Wurth_691236510002]
J6  691236510003  [Wurth_691236510003]
J7  HTSW-102-07-G-S  [Samtec_HTSW-102-07-G-S]
J9  HTSW-102-07-G-S  [Samtec_HTSW-102-07-G-S]
J10  HTSW-102-07-G-S  [Samtec_HTSW-102-07-G-S]
J11  HTSW-102-07-G-S  [Samtec_HTSW-102-07-G-S]
J12  HTSW-102-07-G-S  [Samtec_HTSW-102-07-G-S]
J13  HTSW-102-07-G-S  [Samtec_HTSW-102-07-G-S]
R147  ValueDisplayed: 82.0k  [0402]  (hidden comment: RC0402FR-0782KL)
R148  ValueDisplayed: 110k  [0402]  (hidden comment: CRCW0402110KFKED)
R149  ValueDisplayed: 4.70k  [0402]  (hidden comment: RC0402FR-074K7L)
R150  ValueDisplayed: 10.0k  [0402]  (hidden comment: RK73H1ETTP1002F)
R151  ValueDisplayed: 52.3k  [0402]  (hidden comment: CRCW040252K3FKED)
R152  ValueDisplayed: 10.0k  [0402]  (hidden comment: RK73H1ETTP1002F)
R153  ValueDisplayed: 10.0k  [0402]  (hidden comment: RK73H1ETTP1002F)
R154  ValueDisplayed: 13.0k  [0402]  (hidden comment: CRCW040213K0FKED)
R155  ValueDisplayed: 1.00M  [0402]  (hidden comment: RC0402FR-071ML)
R156  ValueDisplayed: 220k  [0402]  (hidden comment: RC0402FR-07220KL)
R157  ValueDisplayed: 82.0k  [0402]  (hidden comment: RC0402FR-0782KL)
R158  ValueDisplayed: 110k  [0402]  (hidden comment: CRCW0402110KFKED)
R159  ValueDisplayed: 10.0k  [0402]  (hidden comment: RK73H1ETTP1002F)
R160  ValueDisplayed: 10.0k  [0402]  (hidden comment: RK73H1ETTP1002F)
R161  ValueDisplayed: 22.1k  [0402]  (hidden comment: CRCW040222K1FKED)
R162  ValueDisplayed: 13.0k  [0402]  (hidden comment: CRCW040213K0FKED)
SH-J1  60900213421  [Wurth_60900213421]
SH-J2  60900213421  [Wurth_60900213421]
SH-J3  60900213421  [Wurth_60900213421]
SH-J4  60900213421  [Wurth_60900213421]
SH-J5  60900213421  [Wurth_60900213421]
U40  TPSM63603RDHR  [RDH0030A-MFG]
U41  TPSM82912RDUR  [RDU0028A-MFG]
U42  TPSM63603RDHR  [RDH0030A-MFG]
U43  TPS7A9401DSC  [DSC0010J-MFG]

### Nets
GNDB: C99.2 C100.2 C101.2 C102.2 C103.2 C104.2 C105.2 C106.2 C107.2 C108.2 C109.2 C110.2 C111.2 C112.2 C113.2 C114.2 C115.2 C116.2 C117.2 C118.2 C119.2 C120.1 C122.1 C123.1 C124.1 C125.1 C126.1 C127.1 C128.2 C129.2 C130.2 C131.2 C132.1 C133.2 C134.1 C137.2 C138.2 C139.2 J5.2 J6.2 J7.2 R149.1 R150.2 R152.2 R153.2 R154.1 R156.2 R158.2 R161.1 U40.5(PGND) U40.6(PGND) U40.16(PGND) U40.17(PGND) U40.24(AGND) U40.27(AGND) U40.28(PGND) U40.29(PGND) U41.1(PGND) U41.2(PGND) U41.3(PGND) U41.5(PGND) U41.6(PGND) U41.7(PGND) U41.8(PGND) U41.9(PGND) U41.16(PGND) U41.17(PGND) U41.20(PSNS) U41.25(PGND) U41.26(PGND) U41.28(PGND) U42.7(VOUT) U42.8(VOUT) U42.9(VOUT) U42.10(VOUT) U42.12(VOUT) U42.13(VOUT) U42.14(VOUT) U42.15(VOUT) U42.22(VLDOIN) U42.30(VOUT) U43.4(PG) U43.6(GND) U43.11(Thermal_Pad)
VDD_3V3: C128.1 C129.1 C130.1 R155.1 U43.8(SNS) U43.9(OUT) U43.10(OUT)
VDD_5V: C118.1 C119.1 C131.1 FB2.1 J11.2 U43.1(IN) U43.2(IN) U43.3(EN)
VDD_5V_C2K: C116.1 C117.1 FB2.2
VDD_12VN: C123.2 C124.2 J13.2
VDD_12VN_0: C121.2 C122.2 C125.2 C126.2 C127.2 C135.2 C136.2 J12.2 J13.1 R159.2 R160.2 R162.1 U42.5(PGND) U42.6(PGND) U42.16(PGND) U42.17(PGND) U42.24(AGND) U42.27(AGND) U42.28(PGND) U42.29(PGND)
VDD_12VP: C103.1 C104.1 C105.1 C106.1 J10.2 U41.18(VIN) U41.24(EN/SYNC)
VDD_12VP_0: C100.1 C101.1 C102.1 J9.2 J10.1 R148.2 U40.7(VOUT) U40.8(VOUT) U40.9(VOUT) U40.10(VOUT) U40.12(VOUT) U40.13(VOUT) U40.14(VOUT) U40.15(VOUT) U40.22(VLDOIN) U40.30(VOUT)
VDD_15VN: C132.2 C134.2 J6.3 J12.1
VDD_15VP: C107.1 C108.1 C109.1 C133.1 C135.1 C136.1 C138.1 C139.1 J5.1 J6.1 J7.1 J9.1 R147.2 R157.2 U40.3(VIN) U40.4(VIN) U40.18(VIN) U40.19(VIN) U42.3(VIN) U42.4(VIN) U42.18(VIN) U42.19(VIN)
NetC99_1: C99.1 U40.23(VCC)
NetC110_1: C110.1 C111.1 C112.1 FB1.1 U41.10(VOUT) U41.11(VOUT) U41.12(VOUT) U41.13(VOUT) U41.14(VOUT) U41.15(VOUT) U41.27(VOUT)
NetC113_1: C113.1 C114.1 C115.1 FB1.2 J11.1 R151.2
NetC120_2: C120.2 U41.21(NR/SS)
NetC121_1: C121.1 U42.23(VCC)
NetC137_1: C137.1 R161.2 U43.7(NR/SS)
NetR147_1: R147.1 R150.1 U40.2(EN/SYNC)
NetR148_1: R148.1 R152.1 U40.25(FB)
NetR149_2: R149.2 U41.23(S-CONF)
NetR151_1: R151.1 R153.1 U41.22(FB)
NetR154_2: R154.2 U40.1(RT)
NetR155_2: R155.2 R156.1 U43.5(FB_PG)
NetR157_1: R157.1 R159.1 U42.2(EN/SYNC)
NetR158_1: R158.1 R160.1 U42.25(FB)
NetR162_2: R162.2 U42.1(RT)
NetU40_20: U40.20(CBOOT) U40.21(RBOOT)
NetU42_20: U42.20(CBOOT) U42.21(RBOOT)

Not connected (* = marked no-connect by the designer): U40 11(SW) 26(PG); U41 4(SW) 19(PG); U42 11(SW) 26(PG)

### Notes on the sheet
- ON:12V
- Vout=0.8*(1+R1/R2)=5V
- Vout = 150uA*Rnr = 3.3V
- (near J6) Input +15V

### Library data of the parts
C99 C121 = CMP-0081259-1: CAP, CERM, 1 µF, 35 V,+/- 10%, X7R, AEC-Q200 Grade 1, 0603; Manufacturer: TDK; SizeAreaWB_mm2: 4.68; SizeArea_mm2: 1.28; AEC Qualified: Y; AEC Category: Q200; Value: 1uF; TaMax_C: 125°C; SizeZ_mm: 1; Polarized: N; TaMin_C: -55°C; SizeY_mm: 0.8; U/M: EA; SizeX_mm: 1.6
C100 C101 C123 C125 C126 = CMP-0008646-2: CAP, CERM, 47 uF, 25 V, +/- 20%, JB, 1206; Manufacturer: TDK; TaMin_C: -55°C; Polarized: N; SizeAreaWB_mm2: 10.92; Value1: Unknown; U/M: EA; Value: 47uF; TaMax_C: 85°C; SizeZ_mm: 1.35; SizeX_mm: 3.2; SizeY_mm: 1.6; SizeArea_mm2: 5.12; Cap_F: 47µF; AEC Category: Q200
C102 C104 C114 C117 C119 C120 C124 C127 C129 C131 = CMP-0080610-1: CAP, CERM, 0.1 µF, 25 V,+/- 10%, X7R, AEC-Q200 Grade 1, 0402; Manufacturer: TDK; TaMin_C: -55°C; Polarized: N; SizeAreaWB_mm2: 3; U/M: EA; Value: 0.1uF; TaMax_C: 125°C; SizeZ_mm: 0.6; SizeX_mm: 1; SizeY_mm: 0.5; AEC Qualified: Y; Cap_F: 100nF; AEC Category: Q200
C103 = CMP-0084680-1: CAP, CERM, 22 µF, 25 V,+/- 20%, X5R, AEC-Q200 Grade 3, 0805; Manufacturer: MuRata; TaMin_C: -55°C; Polarized: N; SizeAreaWB_mm2: 6.75; U/M: EA; Value: 22uF; TaMax_C: 85°C; SizeZ_mm: 1.45; SizeX_mm: 2; SizeY_mm: 1.25; Cap_Case: 0805; SizeArea_mm2: 2.5; AEC Qualified: Y; AEC Grade: 3; AEC Category: Q200
C105 C109 C122 C134 = CMP-0860997-1: CAP, CERM, 1000 pF, 50 V,+/- 10%, X8R, AEC-Q200 Grade 0, 0402; Manufacturer: TDK; SizeArea_mm2: 0.5; U/M: EA; SizeX_mm: 1; Polarized: N; AEC Grade: 0; AEC Qualified: Y; TaMin_C: -55°C; Value: 1000pF; TaMax_C: 150°C; SizeZ_mm: 0.6; Cap_F: 1nF; SizeAreaWB_mm2: 3; AEC Category: Q200
C106 C108 C133 = CMP-0006674-2: CAP, CERM, 0.01 uF, 50 V, +/- 10%, X7R, 0402; Manufacturer: MuRata; TaMin_C: -55°C; Polarized: N; SizeAreaWB_mm2: 3; Value1: Unknown; U/M: EA; Value: 0.01uF; TaMax_C: 125°C; SizeZ_mm: 0.6; SizeX_mm: 1; SizeY_mm: 0.5; Cap_F: 10nF; AEC Category: Q200
C107 C132 C138 C139 = CMP-0084680-1: CAP, CERM, 22 µF, 25 V,+/- 20%, X5R, AEC-Q200 Grade 3, 0805; Manufacturer: MuRata; SizeX_mm: 2; SizeAreaWB_mm2: 6.75; Cap_Case: 0805; AEC Grade: 3; SizeY_mm: 1.25; SizeArea_mm2: 2.5; SizeZ_mm: 1.45; U/M: EA; Polarized: N; AEC Category: Q200; Value: 22uF; TaMin_C: -55°C; AEC Qualified: Y; TaMax_C: 85°C
C110-C113 = CMP-0081159-1: CAP, CERM, 22 µF, 16 V,+/- 20%, X5R, 0603; Manufacturer: Samsung; SizeAreaWB_mm2: 4.68; SizeArea_mm2: 1.28; AEC Qualified: N; AEC Category: Q200; Value: 22uF; TaMax_C: 85°C; SizeZ_mm: 1; TaMin_C: -55°C; SizeY_mm: 0.8; U/M: EA; SizeX_mm: 1.6
C115 C130 = CMP-0860997-1: CAP, CERM, 1000 pF, 50 V,+/- 10%, X8R, AEC-Q200 Grade 0, 0402; Manufacturer: TDK; TaMin_C: -55°C; Polarized: N; SizeAreaWB_mm2: 3; U/M: EA; Value: 1000pF; TaMax_C: 150°C; SizeZ_mm: 0.6; SizeX_mm: 1; SizeY_mm: 0.5; AEC Qualified: Y; Cap_F: 1nF; AEC Category: Q200; AEC Grade: 0
C116 C118 C128 C137 = CMP-0006564-3: CAP, CERM, 10 uF, 10 V, +/- 20%, X5R, 0402; Manufacturer: MuRata; TaMin_C: -55°C; Polarized: N; SizeAreaWB_mm2: 3; Value1: Unknown; U/M: EA; Value: 10uF; TaMax_C: 85°C; SizeZ_mm: 0.6; SizeX_mm: 1; SizeY_mm: 0.5; Cap_F: 10µF; AEC Category: Q200
C135 C136 = CMP-0007860-1: CAP, CERM, 4.7 uF, 50 V, +/- 10%, X6S, 0805; Manufacturer: TDK; TaMin_C: -55°C; ESR_ohm: 2.346m; Polarized: N; SizeAreaWB_mm2: 6.75; Value1: 0.002346 ohm; U/M: EA; Value: 4.7uF; TaMax_C: 105°C; SizeZ_mm: 1.45; SizeX_mm: 2; SizeY_mm: 1.25; Cap_Case: 0805; SizeArea_mm2: 2.5; Cap_F: 4.7µF; IRMS_A: 4.2602A; AEC Category: Q200
FB1 FB2 = CMP-0003237-1: Ferrite Bead, 120 ohm @ 100 MHz, 1.2 A, 0402; Manufacturer: Wurth Elektronik; DCR_ohm: 90m; Imax_A: 1.2A; SizeZ_mm: 0.6; Ztyp@1GHz_Ohm: 167.229; ZTyp@100MHz_Ohm: 120; SizeAreaWB_mm2: 3; Value1: 0.09 ohm; Value: 120 ohm; SizeX_mm: 1; SizeY_mm: 0.5
J5 = CMP-0079044-1: Terminal Block, 5.08mm, 2x1, R/A, TH; Manufacturer: Wurth Elektronik; Pitch_mm: 5.08; Cert_VDE: Y; Gender: Female; Voltage_V: 300V; Current_A: 20A; Row_Count: 1
J6 = CMP-0079043-1: Terminal Block, 5.08mm, 3x1, R/A, TH; Manufacturer: Wurth Elektronik; Pitch_mm: 5.08; Cert_VDE: Y; Gender: Female; Voltage_V: 300V; Current_A: 20A; Row_Count: 1
J7 J9-J13 = CMP-0075483-1: Header, 100mil, 2x1, Gold, TH; Manufacturer: Samtec; Green_REACh: Passed; CT: False; Green_Lifecycle: Active; CNHeader: True
R147 R157 = CMP-0026744-1: RES, 82.0 k, 1%, 0.063 W, 0402; Manufacturer: Yageo America; Power_W: 63mW; TempCo: 100 ppm/C; Value_Code: 82k0; U/M: EA; Value: 82.0k; Res_ohm: 82k; SizeX_mm: 1; SizeY_mm: 0.5; SizeZ_mm: 0.6; Value2: 0.063W; AEC Qualified: N; VDC_V: 50V; AEC Category: Q200
R148 R158 = CMP-0025967-2: RES, 110 k, 1%, 0.063 W, 0402; Manufacturer: Vishay-Dale; Power_W: 63mW; TempCo: 100 ppm/C; U/M: EA; Value: 110k; EIA_Code: E96; SizeY_mm: 0.5; SizeZ_mm: 0.6; Value2: 0.063W; VDC_V: 50V; AEC Category: Q200; SizeX_mm: 1
R149 = CMP-0026739-1: RES, 4.70 k, 1%, 0.0625 W, 0402; Manufacturer: Yageo America; Power_W: 62.5mW; TempCo: 100 ppm/C; Value_Code: 4k70; U/M: EA; Value: 4.70k; Res_ohm: 4.7k; SizeX_mm: 1; SizeY_mm: 0.5; SizeZ_mm: 0.6; AEC Qualified: N; VDC_V: 50V; AEC Category: Q200
R150 R152 R153 R159 R160 = CMP-0026748-1: as R9 on sheet FVI80_Power_OPA593
R151 = CMP-0026441-2: RES, 52.3 k, 1%, 0.063 W, AEC-Q200 Grade 0, 0402; Manufacturer: Vishay-Dale; Power_W: 63mW; TempCo: 100 ppm/C; Value_Code: 52k3; Value: 52.3k; EIA_Code: E96; SizeX_mm: 1; SizeY_mm: 0.5; SizeZ_mm: 0.6; Value2: 0.063W; AEC Qualified: Y; VDC_V: 50V; AEC Category: Q200; AEC Grade: 0
R154 R162 = CMP-0026003-2: RES, 13.0 k, 1%, 0.063 W, 0402; Manufacturer: Vishay-Dale; Power_W: 63mW; TempCo: 100 ppm/C; Value_Code: 13k0; U/M: EA; Value: 13.0k; EIA_Code: E96; Res_ohm: 13k; SizeX_mm: 1; SizeY_mm: 0.5; SizeZ_mm: 0.6; Value2: 0.063W; VDC_V: 50V; AEC Category: Q200
R155 = CMP-0026727-1: RES, 1.00 M, 1%, 0.063 W, 0402; Manufacturer: Yageo America; Power_W: 63mW; TempCo: 100 ppm/C; Value_Code: 1M00; U/M: EA; Value: 1.00Meg; EIA_Code: E96; Res_ohm: 1M; SizeX_mm: 1; SizeY_mm: 0.5; SizeZ_mm: 0.6; Value2: 0.063W; AEC Category: Q200
R156 = CMP-0026728-1: RES, 220 k, 1%, 0.0625 W, 0402; Manufacturer: Yageo America; Power_W: 62.5mW; TempCo: 100 ppm/C; U/M: EA; Value: 220k; SizeX_mm: 1; SizeY_mm: 0.5; SizeZ_mm: 0.6; AEC Qualified: N; VDC_V: 50V; AEC Category: Q200
R161 = CMP-0026178-1: RES, 22.1 k, 1%, 0.063 W, 0402; Manufacturer: Vishay-Dale; Power_W: 63mW; TempCo: 100 ppm/C; Value_Code: 22k1; U/M: EA; Value: 22.1k; EIA_Code: E96; SizeX_mm: 1; SizeY_mm: 0.5; SizeZ_mm: 0.6; Value2: 0.063W; VDC_V: 50V; AEC Category: Q200
SH-J1-SH-J5 = CMP-0003761-2: Shunt, 2.54mm, Gold, Black; Manufacturer: Wurth Elektronik
U40 U42 = CMP-0090663-2: TPSM63603 Cruzline Power Module; Manufacturer: Texas Instruments; Max Supply Voltage: 36V; AEC Category: Q200; Number Of Outputs: 1; Min Supply Voltage: 3V; Output Type: AdjustableProgrammable; TJmax_C: +125°C; Switching Topology: Buck; TaMin_C: -40°C; CompType: IC; Nominal Supply Current: 9uA; Switching Frequency: 200-2200kHz; SizeZ_mm: 1.9mm; Standoff Height: 0mm; Output Voltage: 1-12V; TaMax_C: +105°C
U41 = CMP-0094706-3: 3-V to 17-V, 2-A Low Noise and Low Ripple Buck Converter Module with Integrated Ferrite Bead Filter Compensation; Manufacturer: Texas Instruments; Nominal Supply Current: 5mA; Standoff Height: 0mm; TJmax_C: +125°C; Max Duty Cycle: 100%; Max Supply Voltage: 17V; CompType: IC; AEC Qualified: No; Switching Frequency: 1/2.2MHz; Output Voltage: 0.8-5.5V; Number Of Outputs: 1; Min Supply Voltage: 3V; AEC Category: Q200; Output Type: AdjustableProgrammable; SizeZ_mm: 1.9mm
U43 = CMP-0091022-1: 1-A, Ultra-Low Noise, Ultra-High PSRR, RF Voltage Regulator; Manufacturer: Texas Instruments; Max Supply Voltage: 5.5V; Accuracy Percentage: 1-1.5%; SizeZ_mm: 0.8mm; Output Type: AdjustableProgrammable; Min Supply Voltage: 1.7V; TJmax_C: +150°C; Dropout Voltage: 210mV; AEC Qualified: No; Standoff Height: 0mm; Output Voltage: 0.4-5.3V; Number Of Outputs: 1; Nominal Supply Current: 15-47mA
